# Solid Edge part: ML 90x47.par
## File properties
Title: ML 90x47
Author: DESYS
Template: Iso Part.par
Last saved by: Administrator
Revision: 20
Application: Solid Edge
Tipo di contenuto documento: 0
Accuracy: 0,990
Document Number: 3005
Revision: 0
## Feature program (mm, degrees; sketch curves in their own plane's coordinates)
sketch for "unnamed Protrusion 1" plane through (10.8674, 0, 10.8674) normal (0, -1, 0) x-axis (1, 0, 0)
  line (-470.8674, -245.8674) -> (449.1326, -245.8674)
  line (449.1326, -245.8674) -> (449.1326, 224.1326)
  line (449.1326, 224.1326) -> (-470.8674, 224.1326)
  line (-470.8674, 224.1326) -> (-470.8674, -245.8674)
  dimension (linear) = 449.1326
  dimension (linear) = 449.1326
extrude "unnamed Protrusion 1" add finite 50 along -normal
sketch for "ProtrusioneEstrusa_2" plane through (0, 50, 0) normal (0, 1, 0) x-axis (1, 0, 0)
  line (-200, -235) -> (200, -235)
  line (200, -235) -> (200, 115)
  line (200, 115) -> (-200, 115)
  line (-200, 115) -> (-200, -235)
  dimension (linear) = 200
  dimension (linear) = 200
extrude "ProtrusioneEstrusa_2" add finite 90 along +normal
sketch for "ProtrusioneEstrusa_3" plane through (0, 50, 0) normal (0, 1, 0) x-axis (1, 0, 0)
  line (0, 0) -> (0, 0)
  line (-415, -210) -> (415, -210)
  line (415, -210) -> (415, 210)
  line (415, 210) -> (-415, 210)
  line (-415, 210) -> (-415, -210)
  dimension (linear) = 415
  dimension (linear) = 415
extrude "ProtrusioneEstrusa_3" add finite 60 along +normal
sketch for "ScavoEstrusione_3" plane through (0, 0, 0) normal (0, -1, 0) x-axis (0, 0, 1)
  line (-220, -445) -> (220, -445)
  line (220, -445) -> (220, 445)
  line (220, 445) -> (-220, 445)
  line (-220, 445) -> (-220, -445)
extrude "ScavoEstrusione_3" cut finite 10 along -normal
sketch for "ScavoEstrusione_1" #1 plane through (0, 80, -210) normal (0, 0, -1) x-axis (1, 0, 0)
  arc centre (209.8613, 349.872) radius 380 from (200, -30) to (415, 30) ccw
  line (415, 30) -> (452.6764, 30)
  line (452.6764, -115.2661) -> (452.6764, 30)
  line (200, -115.2661) -> (452.6764, -115.2661)
  line (200, -30) -> (200, -115.2661)
sketch for "ScavoEstrusione_1" #2 plane through (0, 80, -210) normal (0, 0, -1) x-axis (1, 0, 0)
  arc centre (-209.8613, 349.872) radius 380 from (-415, 30) to (-200, -30) ccw
  line (-200, -30) -> (-200, -134.1671)
  line (-200, -134.1671) -> (-465.2028, -134.1671)
  line (-465.2028, 30) -> (-465.2028, -134.1671)
  line (-415, 30) -> (-465.2028, 30)
extrude "ScavoEstrusione_1" cut finite 1320 along -normal
sketch for "unnamed Cutout 1" plane through (460, 25, 0) normal (1, 0, 0) x-axis (0, 0, 1)
  line (-210, -25) -> (-255.6951, -25)
  line (-255.6951, -25) -> (-255.6951, -140.363)
  line (-255.6951, -140.363) -> (-115, -140.363)
  line (-115, -85) -> (-115, -140.363)
  arc centre (-111.9995, 24.9591) radius 110 from (-210, -25) to (-115, -85) ccw
extrude "unnamed Cutout 1" cut through along -normal
sketch for "ScavoEstrusione_4" plane through (0, 70, 100) normal (0, 0, 1) x-axis (-1, 0, 0)
  line (-140, -40) -> (140, -40)
  arc centre (151.6009, 159.6633) radius 200 from (140, -40) to (325, 60) ccw
  line (325, 60) -> (325, 99.6017)
  line (-325, 99.6017) -> (325, 99.6017)
  line (-325, 60) -> (-325, 99.6017)
  arc centre (-151.6009, 159.6633) radius 200 from (-140, -40) to (-325, 60) cw
  dimension (linear) = 140
extrude "ScavoEstrusione_4" cut finite 200 along -normal  Profile_Plane1_Distance = 135 mm
draft "Spoglia_2"  Angles1 = 50 deg
draft "Spoglia_3"  Angles1 = 5 deg
sketch for "ScavoEstrusione_5" plane through (0, 18.0435, 18.0435) normal (1, 0, 0) x-axis (0, 1, 0)
  line (144.3482, -108.0435) -> (101.9565, -108.0435)
  line (101.9565, -108.0435) -> (101.9565, 92.7274)
  line (101.9565, 92.7274) -> (6.9565, 92.7274)
  line (6.9565, 92.7274) -> (6.9565, 196.9565)
  line (6.9565, 196.9565) -> (148.2952, 196.9565)
extrude "ScavoEstrusione_5" cut finite 350 symmetric
sketch for "unnamed Cutout 2" plane through (0, 70, 235) normal (0, 0, 1) x-axis (-1, 0, 0)
  arc centre (0, -146.6071) radius 146.6071 from (-125, -70) to (125, -70) cw
extrude "unnamed Cutout 2" cut through along -normal
sketch for "unnamed Cutout 3" #1 plane through (0, 70, 235) normal (0, 0, 1) x-axis (-1, 0, 0)
  line (125, -10) -> (115, -10)
  arc centre (115, 0) radius 10 from (115, 10) to (115, -10) ccw
  line (115, 10) -> (125, 10)
  arc centre (125, 0) radius 10 from (125, -10) to (125, 10) ccw
sketch for "unnamed Cutout 3" #2 plane through (0, 70, 235) normal (0, 0, 1) x-axis (-1, 0, 0)
  line (-125, -10) -> (-115, -10)
  line (-115, 10) -> (-125, 10)
  dimension (linear) = 115
extrude "unnamed Cutout 3" cut through along -normal
fillet "Rotondo_1" radius 30
sketch for "Foro_1" plane through (0, 10, 120) normal (0, -1, 0) x-axis (0, 0, 1)
  hole centre (50, 0) bore radius 17.5
hole "Foro_1" diameter 35 through
sketch for "ProtrusioneEstrusa_4" plane through (0, 120, -18.4901) normal (0, 1, 0) x-axis (0, 0, 1)
  circle centre (18.4901, 0) radius 35
extrude "ProtrusioneEstrusa_4" add finite 45 along +normal
sketch for "Foro_2" plane through (0, 165, 0) normal (0, 1, 0) x-axis (-1, 0, 0)
  hole centre (0, 0) bore radius 25
hole "Foro_2" diameter 50 through
sketch for "ProtrusioneEstrusa_5" plane through (0, 18.407, 18.407) normal (1, 0, 0) x-axis (0, 1, 0)
  line (135.6089, 62.0377) -> (135.6089, 8.8564)
  line (135.6089, 8.8564) -> (96.2921, 8.8564)
  line (96.2921, 8.8564) -> (96.2921, 75.1839)
  line (96.2921, 75.1839) -> (-2.0897, 85.7605)
  line (-2.0897, 85.7605) -> (-2.0897, 125.0843)
  line (-2.0897, 125.0843) -> (77.9252, 121.993)
  arc centre (75.6089, 62.0377) radius 60 from (77.9252, 121.993) to (135.6089, 62.0377) cw
extrude "ProtrusioneEstrusa_5" add finite 30 symmetric
sketch for "Foro_3" plane through (25.0453, 25.0453, 0) normal (0, 0, -1) x-axis (-1, 0, 0)
  hole centre (25.0453, -0.0453) bore radius 10
hole "Foro_3" diameter 20 to key point
fillet "Rotondo_2" radius 5
fillet "Rotondo_3" radius 10
fillet "Rotondo_4" radius 10
fillet "Rotondo_5" radius 5
fillet "Rotondo_6" radius 10
fillet "Rotondo_7" radius 5
fillet "Rotondo_9" radius 30
fillet "Rotondo_14" radius 10
fillet "Rotondo_15" radius 10
fillet "Rotondo_16" radius 5
fillet "Rotondo_17" radius 10
fillet "Rotondo_18" radius 5
fillet "Rotondo_19" radius 10
fillet "Rotondo_20" radius 5
sketch for "unnamed Cutout 4" plane through (-209.8613, 110, 28.4507) normal (0, 1, 0) x-axis (0, 0, -1)
extrude "unnamed Cutout 4" cut to key point along -normal
fillet "Rotondo_21" radius 10
fillet "Rotondo_22" radius 5
fillet "Rotondo_23" radius 30
fillet "Rotondo_24" radius 5
mirror "unnamed Mirror 1" of "unnamed Cutout 4", "Rotondo_21", "Rotondo_22", "Rotondo_23", "Rotondo_24" about plane through (0, 44.0896, 44.0896) normal (-1, 0, 0)
extrude "unnamed Cutout 5" cut finite 60
fillet "unnamed Round 1"
fillet "unnamed Round 2"
fillet "unnamed Round 3"
fillet "unnamed Round 4"
fillet "Rotondo_29" radius 10
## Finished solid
Body 1: solid body, 203 faces, 477 edges, 278 vertices.
  Faces by surface: cylinder 84, plane 45, blend 36, torus 32, spline 4, sphere 2
  Edges by curve: line 193, circle 157, intersection 75, ellipse 36, curve on surface 16
Bounding box of the edges (mm; curved faces can reach further): 920.000 x 165.000 x 470.000, from (-460, 0, -235) to (460, 165, 235).
Cylindrical faces by radius (mm): R5 x52, R10 x18, R17.5 x1, R25 x1, R30 x4, R35 x1, R60 x1, R110 x1, R146.6071 x1, R200 x2, R380 x2
Toroidal faces (ring radius, tube radius in mm): R5 r5 x12, R22.5 r5 x1, R25 r5 x4, R30 r5 x1, R35 r5 x2, R35 r10 x1, R44.4524 r10 x1, R45 r10 x1, R55 r5 x2, R156.6071 r10 x1, R370 r10 x2, R375 r5 x4
Spherical faces by radius (mm): R5 x2
Planar faces by outward normal: +x 5, +y 12, +z 9, -x 5, -y 5, -z 6, oblique 3
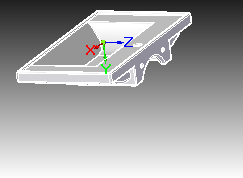
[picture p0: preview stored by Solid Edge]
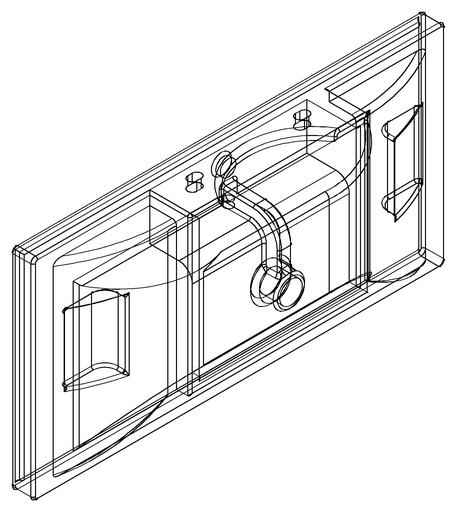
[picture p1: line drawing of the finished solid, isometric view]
